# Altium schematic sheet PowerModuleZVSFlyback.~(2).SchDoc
size 431 x 279 mm; Date: Not shown in title block; ApprovedBy: Not shown in title block; CheckedBy: Not shown in title block; Author: Not shown in title block; CompanyName: Not shown in title block; Engineer: Not shown in title block; Organization: Not shown in title block; Address1: Not shown in title block; Address2: Not shown in title block; Address3: Not shown in title block; Address4: Not shown in title block; DocumentNumber: 1; Revision: Use project parameter SCH_Rev; SheetNumber: 3; SheetTotal: 3; PageSetup: Record=PageOptions¦CenterHorizontal=True¦CenterVertical=True¦PrintScale=1.00¦XCorrection=1.00¦YCorrection=1.00¦PrintKind=0¦BorderSize=5000000¦LeftOffset=0¦BottomOffset=0¦Orientation=2¦PaperLength=1000¦PaperWidth=1000¦Scale=100¦PaperSource=15¦PrintQuality=600¦MediaType=1¦DitherType=10¦PaperKind=Letter¦PrintScaleMode=1
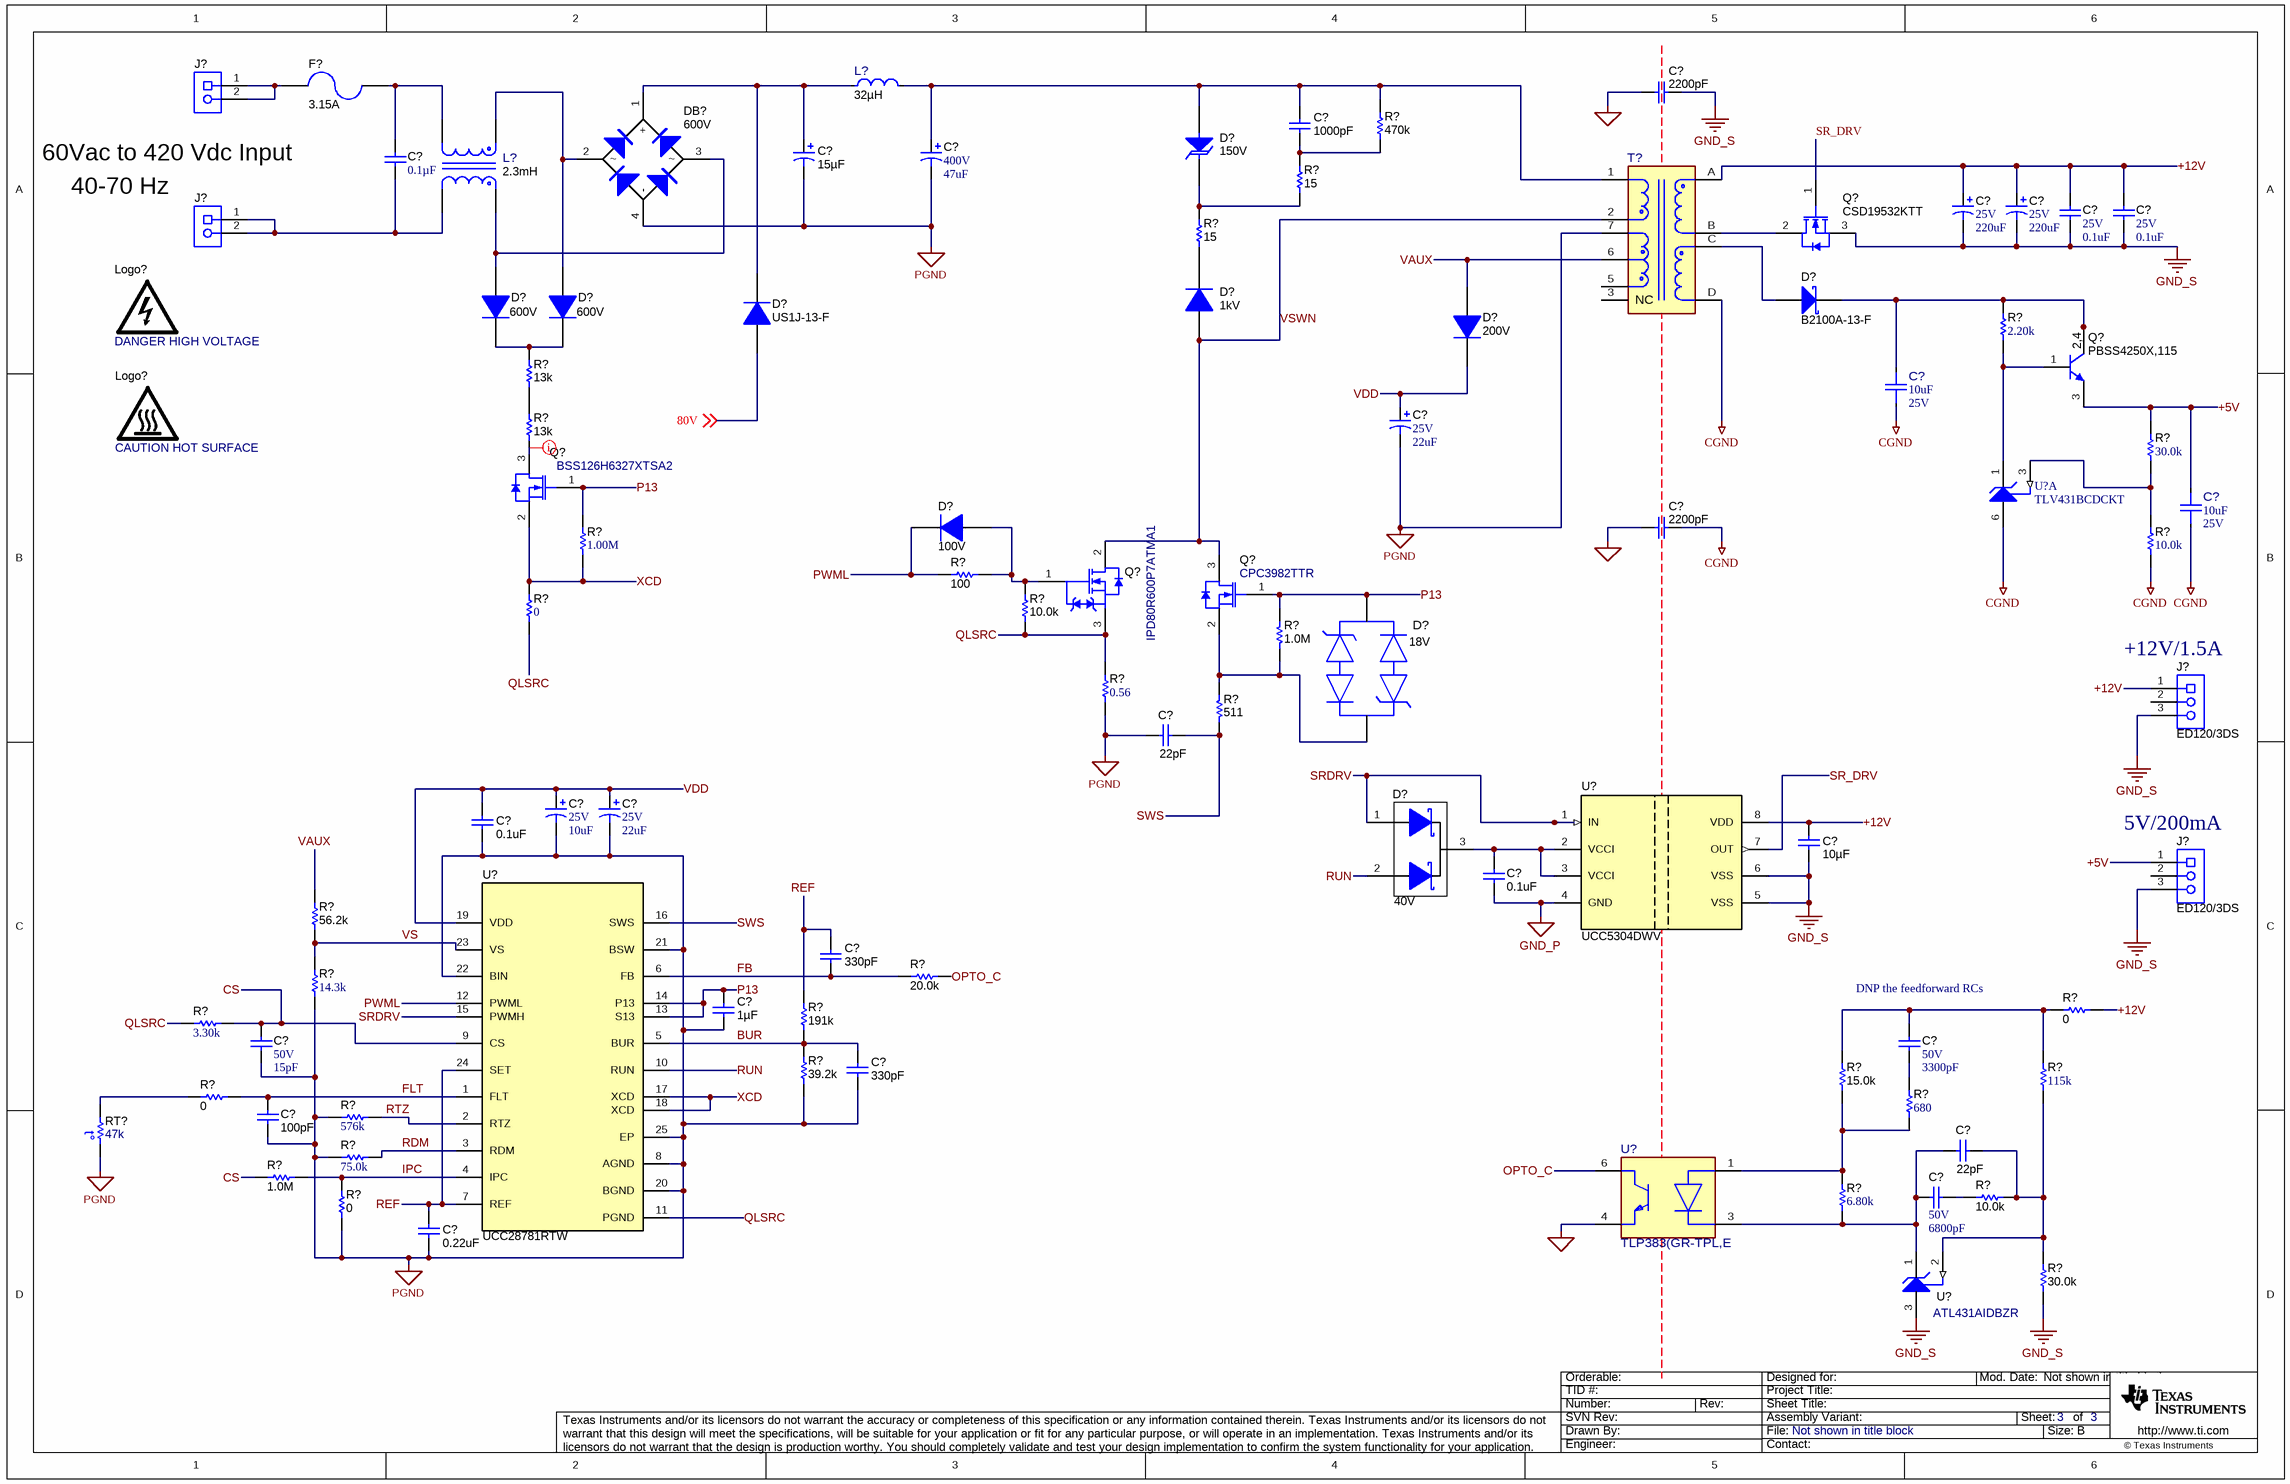
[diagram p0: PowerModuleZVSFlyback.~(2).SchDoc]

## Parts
(Parts that share a designator on the sheet are numbered #1, #2 ... from top to bottom, then left to right.)
C?#1  ValueDisplayed: 2200pF  [C900_9x13]  (hidden comment: C921U222MVVDBA7317)
C?#2  ValueDisplayed: 1000pF  [1206L]  (hidden comment: GRM31BR72J102KW01L)
C?#3  ValueDisplayed: 0.1µF  [B32933_600x1500x2650]  (hidden comment: B32933A3104K000)
C?#4  ValueDisplayed: 15µF  [UVC_1000x1600]  (hidden comment: UVC2G150MPD)
C?#5  VDC_V: 400V  ValueDisplayed: 47uF  [CAPPR7.5-16x25]  (hidden comment: UCS2G470MHD)
C?#6  VDC_V: 25V  ValueDisplayed: 220uF  [BT_1000x1250]  (hidden comment: UBT1E221MPD1TD)
C?#7  VDC_V: 25V  ValueDisplayed: 220uF  [BT_1000x1250]  (hidden comment: UBT1E221MPD1TD)
C?#8  VDC_V: 25V  ValueDisplayed: 0.1uF  [0603]  (hidden comment: 06033D104KAT2A)
C?#9  VDC_V: 25V  ValueDisplayed: 0.1uF  [0603]  (hidden comment: 06033D104KAT2A)
C?#10  ValueDisplayed: 10uF  VDC_V: 25V  [FP-ZRB18AR61E106ME01L_0603-MFG]  (hidden comment: ZRB18AR61E106ME01L)
C?#11  VDC_V: 25V  ValueDisplayed: 22uF  [SM_RADIAL_D]  (hidden comment: EEE-FC1E220P)
C?#12  ValueDisplayed: 2200pF  [C900_9x13]  (hidden comment: C921U222MVVDBA7317)
C?#13  ValueDisplayed: 10uF  VDC_V: 25V  [FP-ZRB18AR61E106ME01L_0603-MFG]  (hidden comment: ZRB18AR61E106ME01L)
C?#14  ValueDisplayed: 22pF  [0402S]  (hidden comment: GCM1555C1H220JA16D)
C?#15  VDC_V: 25V  ValueDisplayed: 10uF  [CAPSMT_62_D55]  (hidden comment: EMVA250ADA100MD55G)
C?#16  VDC_V: 25V  ValueDisplayed: 22uF  [SM_RADIAL_D]  (hidden comment: EEE-FC1E220P)
C?#17  ValueDisplayed: 0.1uF  [0402S]  (hidden comment: GRM155R71H104ME14D)
C?#18  ValueDisplayed: 10µF  [1206_180L]  (hidden comment: C1206C106J3RACAUTO)
C?#19  ValueDisplayed: 0.1uF  [0402S]  (hidden comment: GRM155R71H104ME14D)
C?#20  ValueDisplayed: 330pF  [0402S]  (hidden comment: GRM155R71H331KA01D)
C?#21  Cap_F: 1µF  [0603S]  (hidden comment: CGA3E1X7R1V105K080AC)
C?#22  VDC_V: 50V  ValueDisplayed: 15pF  [0402]  (hidden comment: CC0402JRNPO9BN150)
C?#23  VDC_V: 50V  ValueDisplayed: 3300pF  [0402]  (hidden comment: GRM155R71H332KA01D)
C?#24  ValueDisplayed: 330pF  [0402S]  (hidden comment: GRM155R71H331KA01D)
C?#25  ValueDisplayed: 100pF  [0402S]  (hidden comment: GRM1555C1H101JA01D)
C?#26  ValueDisplayed: 22pF  [0402S]  (hidden comment: GCM1555C1H220JA16D)
C?#27  VDC_V: 50V  ValueDisplayed: 6800pF  [0402]  (hidden comment: GRM155R71H682KA88D)
C?#28  ValueDisplayed: 0.22uF  [0402S]  (hidden comment: GRM155R71C224KA12D)
D?#1  VRWM: 150V  [SMA]  (hidden comment: SMAJ150A)
D?#2  Vr_V: 1kV  [SMA]  (hidden comment: MRA4007T3G)
D?#3  B2100A-13-F  [SMA]
D?#4  Vr_V: 600V  [TUMD2SM]  (hidden comment: RFU02VSM6STR)
D?#5  Vr_V: 600V  [TUMD2SM]  (hidden comment: RFU02VSM6STR)
D?#6  US1J-13-F  [SMA]
D?#7  Vr_V: 200V  [SOD-123H]  (hidden comment: CSFMT104-HF)
D?#8  Vr_V: 100V  [SOD-323]  (hidden comment: BAS316,115)
D?#9  CDSOD323-T18C  [FP-CDSOD323-T18C_SOD323-MFG]  (value not drawn)
D?#10  Vr_V: 40V  [SOT-323]  (hidden comment: BAS40W-05-7-F)
DB?  value 600V  [Z4-D]  (hidden comment: Z4DGP406L-HF)
F?  Irating_A: 3.15A  [FUSE_392]  (hidden comment: 39213150000)
J?#1  ED120/2DS  [On-Shore_ED120_2DS]  (value not drawn)
J?#2  ED120/2DS  [On-Shore_ED120_2DS]  (value not drawn)
J?#3  ED120/3DS  [On-Shore_ED120_3DS]
J?#4  ED120/3DS  [On-Shore_ED120_3DS]
L?#1  Ind_H: 32µH  [FP-7447052_PTH_D10MM0-MFG]  (hidden comment: 7447052)
L?#2  Ind_H: 2.3mH  [FP-RLTI-1387_PTH_CMC_0IN38_0IN60-MFG]  (hidden comment: RLTI-1387)
Logo?#1  DANGER HIGH VOLTAGE  [IEC_HighVoltage_Small]  (no BOM)
Logo?#2  CAUTION HOT SURFACE  [IEC_HotSurface_Small]  (no BOM)
Q?#1  CSD19532KTT  [KTT0002A]
Q?#2  PBSS4250X,115  [SOT-89-3]
Q?#3  BSS126H6327XTSA2  [SOT-23L]
Q?#4  IPD80R600P7ATMA1  [DPAK]
Q?#5  CPC3982TTR  [SOT-23L]
R?#1  ValueDisplayed: 470k  [0805_HV1]  (hidden comment: CRCW0805470KJNEA)
R?#2  ValueDisplayed: 15  [0805_HV1]  (hidden comment: CRCW080515R0JNEA)
R?#3  ValueDisplayed: 15  [0805_HV1]  (hidden comment: CRCW080515R0JNEA)
R?#4  ValueDisplayed: 2.20k  [0603]  (hidden comment: RC0603FR-072K2L)
R?#5  ValueDisplayed: 13k  [1206L]  (hidden comment: CRCW120613K0JNEA)
R?#6  ValueDisplayed: 13k  [1206L]  (hidden comment: CRCW120613K0JNEA)
R?#7  ValueDisplayed: 30.0k  [0603]  (hidden comment: RC0603FR-0730KL)
R?#8  ValueDisplayed: 1.00M  [0603]  (hidden comment: MCT06030C1004FP500)
R?#9  ValueDisplayed: 10.0k  [0402]  (hidden comment: ERJ-2RKF1002X)
R?#10  ValueDisplayed: 100  [0805_HV1]  (hidden comment: CRCW0805100RJNEA)
R?#11  ValueDisplayed: 0  [0603]  (hidden comment: RC0603JR-070RL)
R?#12  ValueDisplayed: 10.0k  [0402S]  (hidden comment: CRCW040210K0FKED)
R?#13  ValueDisplayed: 1.0M  [0402S]  (hidden comment: CRCW04021M00JNED)
R?#14  ValueDisplayed: 0.56  [1206]  (hidden comment: ERJ-8RQFR56V)
R?#15  ValueDisplayed: 511  [0402S]  (hidden comment: CRCW0402511RFKED)
R?#16  ValueDisplayed: 56.2k  [0402S]  (hidden comment: CRCW040256K2FKED)
R?#17  ValueDisplayed: 20.0k  [0402S]  (hidden comment: CRCW040220K0FKED)
R?#18  ValueDisplayed: 14.3k  [0402]  (hidden comment: CRCW040214K3FKED)
R?#19  ValueDisplayed: 0  [0402S]  (hidden comment: RC0402JR-070RL)
R?#20  ValueDisplayed: 191k  [0402S]  (hidden comment: CRCW0402191KFKED)
R?#21  ValueDisplayed: 3.30k  [0402]  (hidden comment: RK73H1ETTP3301F)
R?#22  ValueDisplayed: 39.2k  [0402S]  (hidden comment: CRCW040239K2FKED)
R?#23  ValueDisplayed: 15.0k  [0402S]  (hidden comment: CRCW040215K0FKED)
R?#24  ValueDisplayed: 115k  [0402]  (hidden comment: RC1005F1153CS)
R?#25  ValueDisplayed: 0  [0402S]  (hidden comment: CRCW04020000Z0EDHP)
R?#26  ValueDisplayed: 680  [0603]  (hidden comment: RC0603FR-07680RL)
R?#27  ValueDisplayed: 576k  [0402]  (hidden comment: CRCW0402576KFKED)
R?#28  ValueDisplayed: 75.0k  [0402]  (hidden comment: CRCW040275K0FKED)
R?#29  ValueDisplayed: 1.0M  [0402S]  (hidden comment: CRCW04021M00JNED)
R?#30  ValueDisplayed: 6.80k  [0603]  (hidden comment: RC0603FR-076K8L)
R?#31  ValueDisplayed: 10.0k  [0402S]  (hidden comment: CRCW040210K0FKED)
R?#32  ValueDisplayed: 0  [0402S]  (hidden comment: CRCW04020000Z0EDHP)
R?#33  ValueDisplayed: 30.0k  [0402S]  (hidden comment: CRCW040230K0FKED)
RT?  value 47k  [0603S]  (hidden comment: NCP18WB473J03RB)
T?  RLTI-1324  [FP-RLTI-1324_PTH_0IN980_0IN766-MFG]  (value not drawn)
U?#1  TLV431BCDCKT  [DCK0006A_N]  (part A of 2)
U?#2  UCC5304DWV  [DWV0008A]
U?#3  UCC28781RTW  [RTW0024B]
U?#4  TLP383(GR-TPL,E  [FP-TLP383(GR-TPL,E_SO6-4-MFG]
U?#5  ATL431AIDBZR  [DBZ0003A_L]

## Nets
CGND: C?#10.1 C?#12.1 C?#13.1 R?#9.1 T?.D U?#1.6(ANODE)
GND2: C?#1.2 C?#12.2 U?#4.4(Emitter)
GND_P: C?#19.2 U?#2.4(GND)
GND_S: C?#1.1 C?#6.2(-) C?#7.2(-) C?#8.2 C?#9.2 C?#18.2 J?#3.3 J?#4.3 Q?#1.3(S) R?#33.2 U?#2.5(VSS) U?#2.6(VSS) U?#5.3(ANODE)
PGND: C?#4.2(-) C?#5.2(-) C?#11.2(-) C?#14.1 C?#15.2(-) C?#16.2(-) C?#17.2 C?#21.2 C?#22.2 C?#24.2 C?#25.1 C?#28.2 DB?.4(-) R?#14.1 R?#18.1 R?#22.2 R?#27.1 R?#28.1 R?#32.1 RT?.2 T?.7 U?#3.8(AGND) U?#3.20(BGND) U?#3.21(BSW) U?#3.22(BIN) U?#3.25(EP)
80V: D?#6.2(A) ; off-sheet 80V
+5V: C?#13.2 J?#4.1 Q?#2.3(E) R?#7.2
+12V: C?#6.1(+) C?#7.1(+) C?#8.1 C?#9.1 C?#18.1 J?#3.1 R?#19.1 T?.A U?#2.8(VDD)
BUR: C?#24.1 R?#20.2 R?#22.1 U?#3.5(BUR)
CS: C?#22.1 R?#21.2 R?#29.2 U?#3.9(CS)
FB: C?#20.2 R?#17.1 U?#3.6(FB)
FLT: C?#25.2 R?#25.2 U?#3.1(FLT)
IPC: R?#29.1 R?#32.2 U?#3.4(IPC)
OPTO_C: R?#17.2 U?#4.6(Collector)
P13: C?#21.1 D?#9.2 Q?#3.1(G) Q?#5.1(G) R?#8.2 R?#13.2 U?#3.13(S13) U?#3.14(P13)
PWML: D?#8.1(K) R?#10.1 U?#3.12(PWML)
QLSRC: Q?#4.3(S) R?#11.1 R?#12.1 R?#14.2 R?#21.1 U?#3.11(PGND)
RDM: R?#28.2 U?#3.3(RDM)
REF: C?#20.1 C?#28.1 R?#20.1 U?#3.7(REF) U?#3.24(SET)
RTZ: R?#27.2 U?#3.2(RTZ)
RUN: D?#10.2(A) U?#3.10(RUN)
SR_DRV: Q?#1.1(G) U?#2.7(OUT)
SRDRV: D?#10.1(A) U?#2.1(IN) U?#3.15(PWMH)
SWS: C?#14.2 R?#15.1 U?#3.16(SWS)
VAUX: D?#7.2(A) R?#16.1 T?.6
VDD: C?#11.1(+) C?#15.1(+) C?#16.1(+) C?#17.1 D?#7.1(K) U?#3.19(VDD)
VS: R?#16.2 R?#18.2 U?#3.23(VS)
VSWN: D?#2.2(A) Q?#4.2(D) Q?#5.3(D) T?.2
XCD: Q?#3.2(S) R?#8.1 R?#11.2 U?#3.17(XCD) U?#3.18(XCD)
NetC?#2_1: C?#2.1 C?#5.1(+) D?#1.2(A) L?#1.2 R?#1.2 T?.1
NetC?#2_2: C?#2.2 R?#1.1 R?#2.2
NetC?#3_1: C?#3.1 F?.1 L?#2.3
NetC?#3_2: C?#3.2 J?#2.1 J?#2.2 L?#2.2
NetC?#4_1: C?#4.1(+) D?#6.1(K) DB?.1(+) L?#1.1
NetC?#10_2: C?#10.2 D?#3.1(K) Q?#2.2(C) Q?#2.4(C) R?#4.2
NetC?#19_1: C?#19.1 D?#10.3(K) U?#2.2(VCCI) U?#2.3(VCCI)
NetC?#23_1: C?#23.1 R?#19.2 R?#23.2 R?#24.2
NetC?#23_2: C?#23.2 R?#26.2
NetC?#26_1: C?#26.1 C?#27.2 R?#30.1 U?#4.3(Cathode) U?#5.1(CATHODE)
NetC?#26_2: C?#26.2 R?#24.1 R?#31.2 R?#33.1 U?#5.2(REF)
NetC?#27_1: C?#27.1 R?#31.1
NetD?#1_1: D?#1.1(K) R?#2.1 R?#3.2
NetD?#2_1: D?#2.1(K) R?#3.1
NetD?#3_2: D?#3.2(A) T?.C
NetD?#4_1: D?#4.1(K) D?#5.1(K) R?#5.1
NetD?#4_2: D?#4.2(A) DB?.3 L?#2.1
NetD?#5_2: D?#5.2(A) DB?.2 L?#2.4
NetD?#8_2: D?#8.2(A) Q?#4.1(G) R?#10.2 R?#12.2
NetD?#9_1: D?#9.1 Q?#5.2(S) R?#13.1 R?#15.2
NetF?_2: F?.2 J?#1.1 J?#1.2
NetQ?#1_2: Q?#1.2(D) T?.B
NetQ?#2_1: Q?#2.1(B) R?#4.1 U?#1.1(CATHODE)
NetQ?#3_3: Q?#3.3(D) R?#6.2
NetR?#5_2: R?#5.2 R?#6.1
NetR?#7_1: R?#7.1 R?#9.2 U?#1.3(REF)
NetR?#23_1: R?#23.1 R?#26.1 R?#30.2 U?#4.1(Anode)
NetR?#25_1: R?#25.1 RT?.1

Not connected (* = marked no-connect by the designer): J?#3 2; J?#4 2; T? 3(NC) 5

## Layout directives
net class HV: NetQ?#3_3

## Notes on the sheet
- (near J?#1) 60Vac to 420 Vdc Input
- 40-70 Hz
- (near D?#9) 18V
- (near J?#3) +12V/1.5A
- (near J?#4) 5V/200mA
- (near C?#23) DNP the feedforward RCs

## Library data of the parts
C?#1 C?#12 = CMP-0078358-1: CAP, CERM, 2200 pF, X1 400 VAC/Y1 400 VAC, +/- 20%, Y5V, D9xL13mm; Manufacturer: Kemet; Cap_F: 2.2nF; SizeAreaWB_mm2: 121; VAC_X: 400V; SizeArea_mm2: 81; AEC Qualified: N; AEC Category: Q200; Value: 2200pF; TaMax_C: 125°C; SizeZ_mm: 13; TaMin_C: -40°C; SizeY_mm: 9; U/M: EA; AC_Safety: X1Y1; Cap_Case: 9x13mm
C?#2 = CMP-0008909-2: CAP, CERM, 1000 pF, 630 V, +/- 10%, X7R, 1206; Manufacturer: MuRata; TaMin_C: -55°C; Polarized: N; SizeAreaWB_mm2: 10.92; Value1: Unknown; U/M: EA; Value: 1000pF; TaMax_C: 125°C; SizeZ_mm: 1.35; SizeX_mm: 3.2; SizeY_mm: 1.6; Cap_Case: 1206; Value2: 630V; SizeArea_mm2: 5.12; Cap_F: 1nF; AEC Category: Q200
C?#3 = CMP-0077664-2: CAP, Film, 0.1 µF, X2 305 VAC, +/- 10%, AEC-Q200 Grade 2, TH; Manufacturer: TDK; TaMin_C: -40°C; Polarized: N; SizeAreaWB_mm2: 210.0; Value: 0.1uF; TaMax_C: 105°C; VAC_X: 305; SizeZ_mm: 15.0; SizeX_mm: 26.0; SizeY_mm: 5.5; SizeArea_mm2: 143.0; AEC Qualified: Y; Cap_F: 100nF; AEC Grade: 2; AEC Category: Q200
C?#4 = CMP-0860955-2: CAP, AL, 15 µF, 400 V, +/- 20%, AEC-Q200 Grade 2, TH; Manufacturer: Nichicon; SizeArea_mm2: 100; CompType: Capacitor; Value2: 400V; SizeZ_mm: 18; IRMS_A: 180mA; Polarized: Y; SizeX_mm: 10; Value: 15uF; TaMin_C: -40°C; AEC Grade: 2; U/M: EA; SizeAreaWB_mm2: 144; Cap_Case: 10x16; TaMax_C: 105°C; AEC Category: Q200
C?#5 = CMP-0010241-2: CAP, AL, 47 uF, 400 V, +/- 20%, TH; Manufacturer: Nichicon; TaMin_C: -40°C; Polarized: Y; SizeAreaWB_mm2: 324; Value1: Unknown; U/M: EA; Value: 47uF; TaMax_C: 105°C; SizeZ_mm: 25; SizeX_mm: 16; Cap_Case: Radial  16x25mm; SizeArea_mm2: 256; CompType: Capacitor; AEC Qualified: N; Cap_F: 47µF; IRMS_A: 1.18A; AEC Category: Q200
C?#6 C?#7 = CMP-0010527-1: CAP, AL, 220 uF, 25 V, +/- 20%, 0.1 ohm, TH; Manufacturer: Nichicon; TaMin_C: -40°C; ESR_ohm: 1d; Polarized: Y; SizeAreaWB_mm2: 144; Value1: 0.1 ohm; U/M: EA; Value: 220uF; TaMax_C: 125°C; SizeZ_mm: 14.5; SizeX_mm: 10; Cap_Case: 10x12.5mm; SizeArea_mm2: 100; CompType: Capacitor; Cap_F: 220µF; IRMS_A: 6.8dA; AEC Category: Q200
C?#8 C?#9 = CMP-0006758-5: CAP, CERM, 0.1 uF, 25 V, +/- 10%, X5R, 0603; Manufacturer: AVX; TaMin_C: -55°C; ESR_ohm: 0.048; Polarized: N; SizeAreaWB_mm2: 4.68; Value1: 0.048 ohm; U/M: EA; Value: 0.1uF; TaMax_C: 85°C; SizeZ_mm: 1; SizeX_mm: 1.6; SizeY_mm: 0.8; SizeArea_mm2: 1.28; Cap_F: 100nF; IRMS_A: 5.3dA; AEC Category: Q200
C?#10 C?#13 = CMP-0094458-1: 10µF ±20% 25V Ceramic Capacitor X5R 0603 (1608 Metric); Manufacturer: Murata Electronics; SizeZ_mm: 1.2mm; AEC Qualified: No
C?#11 C?#16 = CMP-0010654-1: CAP, AL, 22 uF, 25 V, +/- 20%, 1 ohm, SMD; Manufacturer: Panasonic; TaMin_C: -40°C; ESR_ohm: 1; Polarized: Y; SizeAreaWB_mm2: 84.28; Value1: 1 ohm; U/M: EA; Value: 22uF; TaMax_C: 105°C; SizeZ_mm: 5.4; SizeX_mm: 7.8; SizeY_mm: 6.6; Cap_Case: D; SizeArea_mm2: 51.48; CompType: Capacitor; Cap_F: 22µF; IRMS_A: 1.15dA; AEC Category: Q200
C?#14 C?#26 = CMP-0006348-2: CAP, CERM, 22 pF, 50 V, +/- 5%, C0G/NP0, AEC-Q200 Grade 1, 0402; Manufacturer: MuRata; TaMin_C: -55°C; Polarized: N; SizeAreaWB_mm2: 3; Value1: Unknown; U/M: EA; Value: 22pF; TaMax_C: 125°C; SizeZ_mm: 0.6; SizeX_mm: 1; SizeY_mm: 0.5; Cap_Case: 0402; Value2: 50V; AEC Qualified: Y; AEC Category: Q200
C?#15 = CMP-0010785-1: CAP, AL, 10 uF, 25 V, +/- 20%, SMD; Manufacturer: Chemi-Con; TaMin_C: -40°C; Polarized: Y; SizeAreaWB_mm2: 28.09; Value1: Unknown; U/M: EA; Value: 10uF; TaMax_C: 85°C; SizeZ_mm: 5.2; SizeX_mm: 4.3; Cap_Case: D55; SizeArea_mm2: 18.49; CompType: Capacitor; Cap_F: 10µF; IRMS_A: 24mA; AEC Category: Q200
C?#17 C?#19 = CMP-0006675-2: CAP, CERM, 0.1 uF, 50 V, +/- 20%, X7R, 0402; Manufacturer: MuRata; TaMin_C: -55°C; Polarized: N; SizeAreaWB_mm2: 3; Value1: Unknown; U/M: EA; Value: 0.1uF; TaMax_C: 125°C; SizeZ_mm: 0.6; SizeX_mm: 1; SizeY_mm: 0.5; Cap_Case: 0402; Value2: 50V; Cap_F: 100nF; AEC Category: Q200
C?#18 = CMP-0081062-1: CAP, CERM, 10 µF, 25 V,+/- 5%, X7R, AEC-Q200 Grade 1, 1206; Manufacturer: Kemet; TaMin_C: -55°C; Polarized: N; SizeAreaWB_mm2: 10.92; U/M: EA; Value: 10uF; TaMax_C: 125°C; SizeZ_mm: 1.8; SizeX_mm: 3.2; SizeY_mm: 1.6; Cap_Case: 1206_180; Value2: 25V; SizeArea_mm2: 5.12; AEC Qualified: Y; AEC Grade: 1; AEC Category: Q200
C?#20 C?#24 = CMP-0006687-2: CAP, CERM, 330 pF, 50 V, +/- 10%, X7R, 0402; Manufacturer: MuRata; TaMin_C: -55°C; Polarized: N; SizeAreaWB_mm2: 3; Value1: Unknown; U/M: EA; Value: 330pF; TaMax_C: 125°C; SizeZ_mm: 0.6; SizeX_mm: 1; SizeY_mm: 0.5; Cap_Case: 0402; Value2: 50V; AEC Category: Q200
C?#21 = CMP-0007067-4: CAP, CERM, 1 uF, 35 V, +/- 10%, X7R, AEC-Q200 Grade 1, 0603; Manufacturer: TDK; TaMin_C: -55°C; ESR_ohm: 5.522m; Polarized: N; SizeAreaWB_mm2: 4.68; Value1: 0.005522 ohm; U/M: EA; Value: 1uF; TaMax_C: 125°C; SizeZ_mm: 1; SizeX_mm: 1.6; SizeY_mm: 0.8; Cap_Case: 0603; Value2: 35V; SizeArea_mm2: 1.28; AEC Qualified: Y; IRMS_A: 2.21617A; AEC Category: Q200
C?#22 = CMP-0006304-2: CAP, CERM, 15 pF, 50 V, +/- 5%, C0G/NP0, 0402; Manufacturer: Yageo America; TaMin_C: -55°C; Polarized: N; SizeAreaWB_mm2: 3; Value1: Unknown; U/M: EA; Value: 15pF; TaMax_C: 125°C; SizeZ_mm: 0.6; SizeX_mm: 1; SizeY_mm: 0.5; AEC Category: Q200
C?#23 = CMP-0006688-2: CAP, CERM, 3300 pF, 50 V, +/- 10%, X7R, 0402; Manufacturer: MuRata; TaMin_C: -55°C; Polarized: N; SizeAreaWB_mm2: 3; Value1: Unknown; U/M: EA; Value: 3300pF; TaMax_C: 125°C; SizeZ_mm: 0.6; SizeX_mm: 1; SizeY_mm: 0.5; Cap_F: 3.3nF; AEC Category: Q200
C?#25 = CMP-0006410-2: CAP, CERM, 100 pF, 50 V, +/- 5%, C0G/NP0, 0402; Manufacturer: MuRata; TaMin_C: -55°C; Polarized: N; SizeAreaWB_mm2: 3; Value1: Unknown; U/M: EA; Value: 100pF; TaMax_C: 125°C; SizeZ_mm: 0.6; SizeX_mm: 1; SizeY_mm: 0.5; Cap_Case: 0402; Value2: 50V; AEC Category: Q200
C?#27 = CMP-0006696-2: CAP, CERM, 6800 pF, 50 V, +/- 10%, X7R, 0402; Manufacturer: MuRata; TaMin_C: -55°C; Polarized: N; SizeAreaWB_mm2: 3; Value1: Unknown; U/M: EA; Value: 6800pF; TaMax_C: 125°C; SizeZ_mm: 0.6; SizeX_mm: 1; SizeY_mm: 0.5; Cap_F: 6.8nF; AEC Category: Q200
C?#28 = CMP-0006648-2: CAP, CERM, 0.22 uF, 16 V, +/- 10%, X7R, 0402; Manufacturer: MuRata; TaMin_C: -55°C; Polarized: N; SizeAreaWB_mm2: 3; Value1: Unknown; U/M: EA; Value: 0.22uF; TaMax_C: 125°C; SizeZ_mm: 0.6; SizeX_mm: 1; SizeY_mm: 0.5; Cap_Case: 0402; Value2: 16V; Cap_F: 220nF; AEC Category: Q200
D?#1 = CMP-0084982-1: Diode, TVS, Uni, 150 V, 243 Vc, 400 W, 1.6 A, SMA; Manufacturer: Littelfuse; Vc: 243V; Ipp: 1.6A; RJA_CperW: 120; AEC Qualified: N; Value: 150V; Ppk: 400W; AEC Category: Q101; SizeArea_mm2: 16.3228; SizeAreaWB_mm2: 37.3428; SizeZ_mm: 2.87; Vbr_Max: 185V; SizeX_mm: 5.59; SizeY_mm: 2.92; Vbr_Min: 167V
D?#2 = CMP-0077082-2: Diode, Standard Recovery Rectifier, 1000 V, 1 A, AEC-Q101, SMA; Manufacturer: ON Semiconductor; SizeAreaWB_mm2: 37.3428; SizeArea_mm2: 16.3228; AEC Qualified: Y; TJmax_C: 175°C; AEC Category: Q101; Value: 1000V; SizeZ_mm: 2.87; Green_REACh: Passed; Io_A: 1A; Vf_V: 1.1V; SizeY_mm: 2.92; Green_Lifecycle: Active; SizeX_mm: 5.59; RJC_CperW: 16.2
D?#3 = CMP-0081099-2: Diode, Schottky, 100 V, 2 A, SMA; Manufacturer: Diodes Inc.; SizeZ_mm: 2.87; SizeX_mm: 5.59; AEC Qualified: N; Value2: 0.79V; SizeArea_mm2: 16.3228; Vf_V: 790mV; AEC Category: Q101; TJmax_C: 125°C; Vr_V: 100V; Value: 100V; Io_A: 2A; SizeAreaWB_mm2: 37.3428; SizeY_mm: 2.92
D?#4 D?#5 = CMP-0080762-2: Diode, Standard Recovery Rectifier, 600 V, 0.2 A, 2x1.4mm; Manufacturer: Rohm; SizeArea_mm2: 3.5; AEC Qualified: N; SizeY_mm: 1.4; Io_A: 200mA; SizeZ_mm: 0.8; Vf_V: 2.2V; SizeAreaWB_mm2: 8.4; TJmax_C: 150°C; Value1: 0.2A; SizeX_mm: 2.5; AEC Category: Q101; Value: 600V
D?#6 = CMP-0077027-2: Diode, Ultrafast, 600 V, 1 A, SMA; Manufacturer: Diodes Inc.; Value: 600V; TJmax_C: 150°C; Value1: 1A; Value2: 1.7V; SizeY_mm: 2.92; Green_REACh: Passed; Green_Lifecycle: Active; SizeX_mm: 5.59; AEC Category: Q101; SizeAreaWB_mm2: 37.3428; SizeZ_mm: 2.87; SizeArea_mm2: 16.3228
D?#7 = CMP-0029199-2: Diode, Superfast Rectifier, 200 V, 1 A, 3.5x1.6mm; Manufacturer: Comchip Technology; Vf_V: 950mV; Value: 200V; Value1: 1A; Value2: 0.95V; TJmax_C: 150°C; SizeAreaWB_mm2: 11.7; SizeArea_mm2: 5.6; SizeX_mm: 3.5; SizeY_mm: 1.6; SizeZ_mm: 1; AEC Category: Q101; AEC Qualified: N
D?#8 = CMP-0029006-2: Diode, Ultrafast, 100 V, 0.25 A, SOD-323; Manufacturer: Nexperia; SizeY_mm: 1.35; Value1: 0.25A; SizeAreaWB_mm2: 8.695; SizeZ_mm: 1; Io_A: 250mA; Value2: 1.4V; SizeX_mm: 2.7; Green_REACh: Incomplete; TJmax_C: 150°C; Green_Lifecycle: Not Set; AEC Category: Q101; Value: 100V; SizeArea_mm2: 3.645
D?#9 = CMP-0087587-1: Diode, TVS, Bi, 18 V, SOD-323; Manufacturer: Bourns Inc.; SizeZ_mm: 1.14mm; AEC Qualified: No
D?#10 = CMP-0028437-2: Diode, Schottky, 40 V, 0.2 A, SOT-323; Manufacturer: Diodes Inc.; Io_A: 200mA; Green_Lifecycle: Not Set; SizeAreaWB_mm2: 10.24; Green_REACh: Incomplete; Value1: 0.2A; Value: 40V; SizeZ_mm: 1.1; SizeX_mm: 2.2; Vf_V: 800mV; Value2: 0.8V; SizeArea_mm2: 4.84; AEC Category: Q101
DB? = Z4DGP406L-HF: Diode, P-N-Bridge, 600 V, 4 A, Z4-D; Manufacturer: Comchip Technology; U/M: EA; Vf_V: 0.95; Value1: 4A; Value2: 0.95V; Io_A: 4; Vr_V: 600; TJmax_C: 175; SizeAreaWB_mm2: 126.25; SizeArea_mm2: 85.05; SizeX_mm: 10.5; SizeY_mm: 8.1; SizeZ_mm: 1.55; AEC Category: Q101; AEC Qualified: N; Green_Lifecycle: Not Set; Green_REACh: Incomplete
F? = CMP-0003561-2: Fuse, 3.15 A, 250VAC/VDC, TH; Manufacturer: Littelfuse; VAC_V: 250V
J?#1 J?#2 = CMP-0074910-1: Terminal Block, 5.08 mm, 2x1, Brass, TH; Manufacturer: On-Shore Technology; Pitch_mm: 5.08; Gender: Female; Shrouded: N; Row_Count: 1; Current_A: 15A; Voltage_V: 300V; Cert_CULUS: Y; CNHeader: False; CT: True; Green_Lifecycle: Not Set; Green_REACh: Incomplete
J?#3 J?#4 = CMP-0074911-1: Terminal Block, 5.08 mm, 3x1, Brass, TH; Manufacturer: On-Shore Technology; Cert_VDE: Y; CNHeader: False; Current_A: 15A; Green_Lifecycle: Not Set; Shrouded: N; Gender: Female; Green_REACh: Incomplete; Voltage_V: 300V; Row_Count: 1; Pitch_mm: 5.08; CT: True
L?#1 = CMP-0087546-1: WE-FI Leaded Toroidal Line Choke; Manufacturer: Wurth; SizeZ_mm: 10mm; Irms: 2.6A; DCR_ohm: 0.045; AEC Qualified: No; Symbol Name: SYM-7447052
L?#2 = CMP-0092946-1: Common Mode Choke, 2.3mH 35%, 0.6x0.38x0.75 IN; Manufacturer: Renco; Test Frequency: 10kHz; SizeZ_mm: 0.75inch; DCR_ohm: 0.03; AEC Qualified: No
Logo?#1 = CMP-0074835-1: IEC 61010-1 High Voltage Warning; SymbolCreator: a0412235
Logo?#2 = CMP-0074837-1: IEC 61010-1 Hot Surface Warning; SymbolCreator: a0412235
Q?#1 = CMP-0000957-3: MOSFET, N-CH, 100 V, 136 A, KTT0002A (TO-263-2); Alternate Manufacturer: None; Manufacturer: Texas Instruments; SizeZ_mm: 4.7; ChType: N; Value2: 44 nC; VdsMax_V: 100V; SizeX_mm: 14.3; SizeAreaWB_mm2: 198.208; SizeY_mm: 10.16; Vgs_V: 20V; QgTyp_nC: 44; Value: 100V; SizeArea_mm2: 145.288; AEC Category: Q101; IdsMax_A: 136A
Q?#2 = CMP-0000491-2: Transistor, NPN, 50 V, 2 A, SOT-89; Manufacturer: NXP Semiconductor; TaMax_C: 150°C; Value1: 2 A; Vcesat1_V: 2.5dV; SizeX_mm: 4.1; SizeY_mm: 4.5; TaMin_C: -65°C; IcRated_A: 2A; CompType: BJT; SizeZ_mm: 1.5; AEC Qualified: N; Value: 50 V; SizeArea_mm2: 18.45; NPN: 1; Vceo_V: 50V; PNP: 0; AEC Category: Q101; SizeAreaWB_mm2: 28.05; U/M: EA
Q?#3 = CMP-0067574-2: MOSFET, N-CH, Depletion Mode, 100 V, 0.17 A, AEC-Q101, SOT-23; Manufacturer: Infineon Technologies; Alternate Manufacturer: None; ChType: N; Value: 600V; Value1: ? ohm; Value2: 1.4 nC; QgTyp_nC: 1.4; Vgs_V: 20V; IdsMax_A: 21mA; SizeAreaWB_mm2: 14.0; SizeArea_mm2: 7.5; SizeX_mm: 2.5; SizeY_mm: 3.0; SizeZ_mm: 1.1; AEC Category: Q101; AEC Qualified: Y
Q?#4 = CMP-0083711-2: MOSFET, N-CH, 800 V, 8 A, DPAK; Manufacturer: Infineon Technologies; Alternate Manufacturer: None; AEC Qualified: N; Vgs_V: 20V; SizeY_mm: 6.54; VdsMax_V: 800V; IdsMax_A: 8A; SizeX_mm: 9.91; Value2: 20 nC; AEC Category: Q101; ChMode: Enhancement; SizeAreaWB_mm2: 101.7114; Value1: ? ohm; SizeArea_mm2: 64.8114; Value: 800V; SizeZ_mm: 2.29; QgTyp_nC: 20
Q?#5 = CMP-0081263-2: MOSFET, N-CH, Depletion Mode, 800 V, SOT-23; Alternate Manufacturer: None; Manufacturer: IXYS; SizeAreaWB_mm2: 14; Vgs_V: 15V; Value1: ? ohm; VdsMax_V: 800V; Value: 800V; SizeZ_mm: 1.1; SizeX_mm: 2.5; SizeY_mm: 3; Value2: ? nC; SizeArea_mm2: 7.5; ChType: N; AEC Category: Q101
R?#1 = CMP-0020554-3: RES, 470 k, 5%, 0.125 W, AEC-Q200 Grade 0, 0805; Manufacturer: Vishay-Dale; Power_W: 125mW; TempCo: 200 ppm/C; Value: 470k; EIA_Code: E24; SizeX_mm: 2; SizeY_mm: 1.25; SizeZ_mm: 1.45; Value2: 0.125W; SizeArea_mm2: 2.5; AEC Qualified: Y; VDC_V: 150V; AEC Category: Q200; AEC Grade: 0
R?#2 R?#3 = CMP-0020464-3: RES, 15, 5%, 0.125 W, AEC-Q200 Grade 0, 0805; Manufacturer: Vishay-Dale; Power_W: 125mW; TempCo: 200 ppm/C; Value_Code: 15R0; Value: 15; EIA_Code: E24; SizeX_mm: 2; SizeY_mm: 1.25; SizeZ_mm: 1.45; Value2: 0.125W; SizeArea_mm2: 2.5; AEC Qualified: Y; VDC_V: 150V; AEC Category: Q200; AEC Grade: 0
R?#4 = CMP-0022986-5: RES, 2.20 k, 1%, 0.1 W, 0603; Manufacturer: Yageo; Power_W: 100mW; TempCo: 100 ppm/C; Value_Code: 2k20; Value: 2.20k; Res_ohm: 2.2k; SizeX_mm: 1.6; SizeY_mm: 0.8; SizeZ_mm: 1; Value2: 0.1W; SizeArea_mm2: 1.28; AEC Qualified: N; VDC_V: 75V; AEC Category: Q200; SizeAreaWB_mm2: 4.68
R?#5 R?#6 = CMP-0018589-3: RES, 13 k, 5%, 0.25 W, AEC-Q200 Grade 0, 1206; Manufacturer: Vishay-Dale; Power_W: 250mW; TempCo: 200 ppm/C; Value_Code: 13k0; Value: 13k; EIA_Code: E24; SizeX_mm: 3.2; SizeY_mm: 1.6; SizeZ_mm: 1.35; Value2: 0.25W; SizeArea_mm2: 5.12; AEC Qualified: Y; VDC_V: 200V; AEC Category: Q200; AEC Grade: 0
R?#7 = CMP-0023020-5: RES, 30.0 k, 1%, 0.1 W, 0603; Manufacturer: Yageo; Power_W: 100mW; TempCo: 100 ppm/C; Value_Code: 30k0; Value: 30.0k; Res_ohm: 30k; SizeX_mm: 1.6; SizeY_mm: 0.8; SizeZ_mm: 1; Value2: 0.1W; SizeArea_mm2: 1.28; AEC Qualified: N; VDC_V: 75V; AEC Category: Q200; SizeAreaWB_mm2: 4.68
R?#8 = CMP-0022731-2: RES, 1.00 M, 1%, 0.125 W, 0603; Manufacturer: Vishay/Beyschlag; Power_W: 125mW; TempCo: 50 ppm/C; Value_Code: 1M00; U/M: EA; Value: 1.00Meg; EIA_Code: E96; Res_ohm: 1M; SizeX_mm: 1.6; SizeY_mm: 0.8; SizeZ_mm: 1; Value2: 0.125W; SizeArea_mm2: 1.28; AEC Qualified: N; VDC_V: 75V; AEC Category: Q200
R?#9 = CMP-0026658-1: RES, 10.0 k, 1%, 0.1 W, 0402; Manufacturer: Panasonic; Power_W: 100mW; TempCo: 100 ppm/C; Value_Code: 10k0; U/M: EA; Value: 10.0k; EIA_Code: E96; Res_ohm: 10k; SizeX_mm: 1; SizeY_mm: 0.5; SizeZ_mm: 0.6; Value2: 0.1W; VDC_V: 50V; AEC Category: Q200
R?#10 = CMP-0020445-3: RES, 100, 5%, 0.125 W, AEC-Q200 Grade 0, 0805; Manufacturer: Vishay-Dale; Power_W: 125mW; TempCo: 200 ppm/C; Value_Code: 100R; Value: 100; EIA_Code: E24; SizeX_mm: 2; SizeY_mm: 1.25; SizeZ_mm: 1.45; Value2: 0.125W; SizeArea_mm2: 2.5; AEC Qualified: Y; VDC_V: 150V; AEC Category: Q200; AEC Grade: 0
R?#11 = CMP-0025885-5: RES, 0, 5%, 0.1 W, 0603; Manufacturer: Yageo; Power_W: 100mW; TempCo: 200 ppm/C; Value_Code: 0000; Value: 0; EIA_Code: E24; SizeX_mm: 1.6; SizeZ_mm: 1; Value2: 0.1W; SizeArea_mm2: 1.28; AEC Qualified: N; VDC_V: 75V; AEC Category: Q200; SizeY_mm: 0.8; SizeAreaWB_mm2: 4.68
R?#12 R?#31 = CMP-0025958-3: RES, 10.0 k, 1%, 0.063 W, AEC-Q200 Grade 0, 0402; Manufacturer: Vishay-Dale; Power_W: 63mW; TempCo: 100 ppm/C; Value_Code: 10k0; Value: 10.0k; EIA_Code: E96; Res_ohm: 10k; SizeX_mm: 1; SizeY_mm: 0.5; SizeZ_mm: 0.6; Value2: 0.063W; AEC Qualified: Y; VDC_V: 50V; AEC Category: Q200; AEC Grade: 0
R?#13 = CMP-0026859-2: RES, 1.0 M, 5%, 0.063 W, AEC-Q200 Grade 0, 0402; Manufacturer: Vishay-Dale; Value: 1.0Meg; Res_ohm: 1M; Value_Code: 1M00; Power_W: 63mW; Value2: 0.063W; VDC_V: 50V; TempCo: 200 ppm/C; SizeArea_mm2: 0.5; SizeX_mm: 1; SizeZ_mm: 0.6; EIA_Code: E24; AEC Category: Q200; AEC Qualified: Y; AEC Grade: 0
R?#14 = CMP-0017792-3: RES, 0.56, 1%, 0.25 W, AEC-Q200 Grade 0, 1206; Manufacturer: Panasonic; Power_W: 250mW; TempCo: 250 ppm/C; Value_Code: R560; Value: 0.56; EIA_Code: E96; SizeX_mm: 3.2; SizeY_mm: 1.6; SizeZ_mm: 1.35; Value2: 0.25W; SizeArea_mm2: 5.12; AEC Qualified: Y; AEC Category: Q200; AEC Grade: 0; SizeAreaWB_mm2: 10.92
R?#15 = CMP-0026436-2: RES, 511, 1%, 0.063 W, AEC-Q200 Grade 0, 0402; Manufacturer: Vishay-Dale; Power_W: 63mW; TempCo: 100 ppm/C; Value_Code: 511R; Value: 511; EIA_Code: E96; SizeX_mm: 1; SizeY_mm: 0.5; SizeZ_mm: 0.6; Value2: 0.063W; AEC Qualified: Y; VDC_V: 50V; AEC Category: Q200; AEC Grade: 0
R?#16 = CMP-0026453-2: RES, 56.2 k, 1%, 0.063 W, AEC-Q200 Grade 0, 0402; Manufacturer: Vishay-Dale; Power_W: 63mW; TempCo: 100 ppm/C; Value_Code: 56k2; Value: 56.2k; EIA_Code: E96; SizeX_mm: 1; SizeY_mm: 0.5; SizeZ_mm: 0.6; Value2: 0.063W; AEC Qualified: Y; VDC_V: 50V; AEC Category: Q200; AEC Grade: 0
R?#17 = CMP-0026162-2: RES, 20.0 k, 1%, 0.063 W, AEC-Q200 Grade 0, 0402; Manufacturer: Vishay-Dale; Power_W: 63mW; TempCo: 100 ppm/C; Value_Code: 20k0; Value: 20.0k; EIA_Code: E96; Res_ohm: 20k; SizeX_mm: 1; SizeY_mm: 0.5; SizeZ_mm: 0.6; Value2: 0.063W; AEC Qualified: Y; VDC_V: 50V; AEC Category: Q200; AEC Grade: 0
R?#18 = CMP-0026016-3: RES, 14.3 k, 1%, 0.063 W, AEC-Q200 Grade 0, 0402; Manufacturer: Vishay-Dale; Power_W: 63mW; TempCo: 100 ppm/C; Value_Code: 14k3; Value: 14.3k; EIA_Code: E96; SizeX_mm: 1; SizeY_mm: 0.5; SizeZ_mm: 0.6; Value2: 0.063W; AEC Qualified: Y; VDC_V: 50V; AEC Category: Q200; AEC Grade: 0
R?#19 = CMP-0027004-2: RES, 0, 5%, 0.063 W, 0402; Manufacturer: Yageo America; Power_W: 63mW; TempCo: 200 ppm/C; Value_Code: 0000; U/M: EA; Value: 0; EIA_Code: E24; SizeX_mm: 1; SizeY_mm: 0.5; SizeZ_mm: 0.6; Value2: 0.063W; VDC_V: 50V; AEC Category: Q200
R?#20 = CMP-0026063-3: RES, 191 k, 1%, 0.063 W, AEC-Q200 Grade 0, 0402; Manufacturer: Vishay-Dale; Power_W: 63mW; TempCo: 100 ppm/C; Value: 191k; EIA_Code: E96; SizeX_mm: 1; SizeY_mm: 0.5; SizeZ_mm: 0.6; Value2: 0.063W; AEC Qualified: Y; VDC_V: 50V; AEC Category: Q200; AEC Grade: 0
R?#21 = CMP-0026750-1: RES, 3.30 k, 1%, 0.063 W, AEC-Q200 Grade 0, 0402; Manufacturer: KOA Speer; Power_W: 63mW; TempCo: 100 ppm/C; Value_Code: 3k30; U/M: EA; Value: 3.30k; Res_ohm: 3.3k; SizeX_mm: 1; SizeY_mm: 0.5; SizeZ_mm: 0.6; Value2: 0.063W; AEC Qualified: Y; VDC_V: 50V; AEC Grade: 0; AEC Category: Q200
R?#22 = CMP-0026327-2: RES, 39.2 k, 1%, 0.063 W, AEC-Q200 Grade 0, 0402; Manufacturer: Vishay-Dale; Power_W: 63mW; TempCo: 100 ppm/C; Value_Code: 39k2; Value: 39.2k; EIA_Code: E96; SizeX_mm: 1; SizeY_mm: 0.5; SizeZ_mm: 0.6; Value2: 0.063W; AEC Qualified: Y; VDC_V: 50V; AEC Category: Q200; AEC Grade: 0
R?#23 = CMP-0026027-3: RES, 15.0 k, 1%, 0.063 W, AEC-Q200 Grade 0, 0402; Manufacturer: Vishay-Dale; Power_W: 63mW; TempCo: 100 ppm/C; Value_Code: 15k0; Value: 15.0k; EIA_Code: E96; Res_ohm: 15k; SizeX_mm: 1; SizeY_mm: 0.5; SizeZ_mm: 0.6; Value2: 0.063W; AEC Qualified: Y; VDC_V: 50V; AEC Category: Q200; AEC Grade: 0
R?#24 = CMP-0077547-1: RES, 115 k, 1%, 0.0625 W, 0402; Manufacturer: Samsung Electro-Mechanics; Power_W: 62.5mW; TempCo: 300 ppm/C; U/M: EA; Value: 115k; EIA_Code: E96; SizeX_mm: 1.0; SizeY_mm: 0.5; SizeZ_mm: 0.6; AEC Qualified: N; VDC_V: 50V; AEC Category: Q200
R?#25 R?#32 = CMP-0081856-1: RES, 0, 0%, 0.2 W, AEC-Q200 Grade 0, 0402; Manufacturer: Vishay-Dale; SizeAreaWB_mm2: 3; SizeArea_mm2: 0.5; AEC Qualified: Y; AEC Category: Q200; Value: 0; SizeZ_mm: 0.6; Power_W: 200mW; VDC_V: 50V; Value2: 0.2W; SizeX_mm: 1
R?#26 = CMP-0023235-5: RES, 680, 1%, 0.1 W, 0603; Manufacturer: Yageo; Power_W: 100mW; TempCo: 100 ppm/C; Value_Code: 680R; Value: 680; SizeX_mm: 1.6; SizeY_mm: 0.8; SizeZ_mm: 1; Value2: 0.1W; SizeArea_mm2: 1.28; AEC Qualified: N; VDC_V: 75V; AEC Category: Q200; SizeAreaWB_mm2: 4.68
R?#27 = CMP-0026455-2: RES, 576 k, 1%, 0.063 W, AEC-Q200 Grade 0, 0402; Manufacturer: Vishay-Dale; Power_W: 63mW; TempCo: 100 ppm/C; Value: 576k; EIA_Code: E96; SizeX_mm: 1; SizeY_mm: 0.5; SizeZ_mm: 0.6; Value2: 0.063W; AEC Qualified: Y; VDC_V: 50V; AEC Category: Q200; AEC Grade: 0
R?#28 = CMP-0026543-2: RES, 75.0 k, 1%, 0.063 W, AEC-Q200 Grade 0, 0402; Manufacturer: Vishay-Dale; Power_W: 63mW; TempCo: 100 ppm/C; Value_Code: 75k0; Value: 75.0k; EIA_Code: E96; Res_ohm: 75k; SizeX_mm: 1; SizeY_mm: 0.5; SizeZ_mm: 0.6; Value2: 0.063W; AEC Qualified: Y; VDC_V: 50V; AEC Category: Q200; AEC Grade: 0
R?#29 = CMP-0026859-2: RES, 1.0 M, 5%, 0.063 W, AEC-Q200 Grade 0, 0402; Manufacturer: Vishay-Dale; Power_W: 63mW; TempCo: 200 ppm/C; Value_Code: 1M00; Value: 1.0Meg; EIA_Code: E24; Res_ohm: 1M; SizeX_mm: 1; SizeY_mm: 0.5; SizeZ_mm: 0.6; Value2: 0.063W; AEC Qualified: Y; VDC_V: 50V; AEC Category: Q200; AEC Grade: 0
R?#30 = CMP-0023253-5: RES, 6.80 k, 1%, 0.1 W, 0603; Manufacturer: Yageo; Power_W: 100mW; TempCo: 100 ppm/C; Value_Code: 6k80; Value: 6.80k; Res_ohm: 6.8k; SizeX_mm: 1.6; SizeY_mm: 0.8; SizeZ_mm: 1; Value2: 0.1W; SizeArea_mm2: 1.28; AEC Qualified: N; VDC_V: 75V; AEC Category: Q200; SizeAreaWB_mm2: 4.68
R?#33 = CMP-0078244-2: RES, 30.0 k, 1%, 0.063 W, AEC-Q200 Grade 0, 0402; Manufacturer: Vishay-Dale; Power_W: 63mW; Green_Lifecycle: Active; TempCo: 100 ppm/C; Value_Code: 30k0; Green_REACh: Passed; Value: 30.0k; Res_ohm: 30k; SizeX_mm: 1; SizeY_mm: 0.5; SizeZ_mm: 0.6; Value2: 0.063W; AEC Qualified: Y; VDC_V: 50V; AEC Grade: 0; AEC Category: Q200
RT? = CMP-0002523-3: Thermistor NTC, 47k ohm, 5%, 0603; Manufacturer: MuRata; TaMax_C: 125°C; SizeX_mm: 1.6; SizeY_mm: 0.8; TaMin_C: -40°C; Power_W: 100mW; SizeZ_mm: 1; SizeArea_mm2: 1.28; SizeAreaWB_mm2: 4.68; U/M: EA
T? = CMP-0087465-1: Lm=200uH, Llk=5uH / P:S1:S2:A = 40:10:10:15; Manufacturer: Renco Electronics; AEC Qualified: No; SizeZ_mm: 0.66inch; DCR_ohm: 0.1; Ind_H: 110µH; Ns1toNp: 2.5:0.5:1:0.5:1
U?#1 = CMP-0033201-3: 0.5% Accuracy Low-Voltage Adjustable Precision Shunt Regulator, DCK0006A (SOT-SC70-6); Manufacturer: Texas Instruments; VO Adj(Max)(V): 6; Initial Accuracy @ 25/deg C(%): 0.5; Eco-Plan: Green (RoHS & no Sb/Br); Iout/Iz(Max)(mA): 15; Rating: Catalog; Temp Coeff(Max)(ppm/ degree C): 129; VO Adj(Min)(V): 1.24; Min Iz for Regulation(uA): 80; AEC Category: Q200; AEC Qualified: N; CompType: IC; SizeAreaWB_mm2: 9.3; SizeArea_mm2: 4.2; SizeX_mm: 2.1; SizeY_mm: 2.0; SizeZ_mm: 1.1
U?#2 = CMP-0860377-2: 4-A/6-A, Single-Channel Reinforced Isolation Gate Driver with High Noise Immunity, DWV0008A (SOIC-8); Manufacturer: Texas Instruments; SizeX_mm: 11.5; SizeArea_mm2: 67.275; SizeAreaWB_mm2: 105.975; CompType: IC; SizeZ_mm: 2.8; SizeY_mm: 5.85; AEC Category: Q200; AEC Qualified: N
U?#3 = CMP-0086087-1: UCC28781RTW, RTW0024B (WQFN-24); Manufacturer: Texas Instruments; SizeY_mm: 4; SizeZ_mm: 0.8; AEC Category: Q200; SizeArea_mm2: 16; CompType: IC; AEC Qualified: N; SizeAreaWB_mm2: 25
U?#4 = CMP-0087394-2: Optoisolator Transistor Output 5000Vrms 1 Channel 6-SO; Manufacturer: Toshiba; CTR (Max): 300%; CTR (Min): 100%; SizeZ_mm: 2.3mm
U?#5 = CMP-0066199-1: 2.5V Low Iq Adjustable Precision Shunt Regulator, DBZ0003A (SOT-23-3); Manufacturer: Texas Instruments; SizeArea_mm2: 7.5; SizeAreaWB_mm2: 14.0; SizeX_mm: 2.5; SizeY_mm: 3.0; SizeZ_mm: 1.12; CompType: IC; U/M: EA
